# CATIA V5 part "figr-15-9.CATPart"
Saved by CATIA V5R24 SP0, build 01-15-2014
Part number: Part1
Bounding box of the stored display mesh (mm): x -50 to 50, y -32.5 to 33.5, z -52 to 1
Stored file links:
  D:\KAVITA\CATIA V5-6R2014 Project_ Kavita\CATIA V5-6R2014_partfiles\Partfiles\c15_catia_v5-6r2014_prt\figr-15-9.CATPart
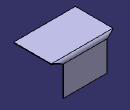
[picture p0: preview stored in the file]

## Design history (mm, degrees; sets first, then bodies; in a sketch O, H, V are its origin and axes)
SheetMetalParameters1: Thickness 1, BendRadius 4, KFactor 0.475772 {= log(min(100,max(20*SheetMetalParameters1.BendRadius,SheetMetalParameters1.Thickness)/SheetMetalParameters1.Thickness))/log(100)/2}, ReliefRadialLength 4, ReliefAxialLength 4, MinimumBendRadius 0
Body1 (main body)
  Sketch1 on xy-plane, origin (0, 0, 0), H (1, 0, 0), V (0, 1, 0)
    line L1 (-50, 32.5) -> (50, 32.5)
    line L2 (50, 32.5) -> (50, -32.5)
    line L3 (50, -32.5) -> (-50, -32.5)
    line L4 (-50, -32.5) -> (-50, 32.5)
    length L1 = 100
    length L2 = 65
    horizontal: L1 H, L3 H
    vertical: L2 V, L4 V
    symmetry: L4 L2 V, L1 L3 H
  Wall1: Thickness 1, Profile Sketch1
  d_NewWallOnEdge1: NewWallOnEdge_Edge edge [face of Wall1 | face of Wall1], NewWallOnEdge_Length 53, NewWallOnEdge_HeightLimitOffset 0, NewWallOnEdge_WidthOffset1 -15, NewWallOnEdge_WidthOffset2 -15, NewWallOnEdge_Angle 90, NewWallOnEdge_BendRadiusValue 4 {= SheetMetalParameters1.BendRadius}, NewWallOnEdge_BendTable SheetMetalParameters1, KFacteur 0.475772 {= log(min(100,max(20*d_NewWallOnEdge1.Radius,SheetMetalParameters1.Thickness)/SheetMetalParameters1.Thickness))/log(100)/2}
